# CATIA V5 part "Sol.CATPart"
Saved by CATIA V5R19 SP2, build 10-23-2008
Part number: Sol
Bounding box of the stored display mesh (mm): x 0 to 6000, y -177 to 177, z -68.836 to 0
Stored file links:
  E:\Mes documents\03_Ressources pédagogiques\01_Catia\Buggy Dassault\SchemaCinematiqueFinal\Sol.CATPart
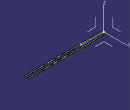
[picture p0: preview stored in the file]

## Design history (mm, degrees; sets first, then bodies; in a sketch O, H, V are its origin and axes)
AxisSystem1: origin (0, 0, 0), X (1, 0, 0), Y (0, 1, 0), Z (0, 0, 1)
Body1 (main body)
  Plane1: type Offset, RefPlane ZX plane of AxisSystem1, Offset 147
  Plane2: type Offset, RefPlane ZX plane of AxisSystem1, Offset 147, reversed
  Sketch1 on Plane1, origin (0, 147, 0), H (-1, 0, 0), V (0, 0, 1)
    spline S1 through (-2519.6694, 0) (-2595.23, 0) (-2761.0478, -2.7637) (-2976.8854, 36.2754) (-3314.4824, -16.625) (-3730.1819, 30.4209) (-3964.2934, -13.9903) (-4260.9327, 31.8924) (-4715.3639, -16.6283) (-4982.808, 0)
    line L1 (-2519.6694, 0) -> (0, 0)
    point P1 (-2519.6694, 0)
    point P2 (0, 0)
    line L2 (-4982.808, 0) -> (-6000, 0)
    point P3 (-4982.808, 0)
    point P4 (-6000, 0)
    reference projected point E1 (0, 0) from edge [YZ plane of AxisSystem1 | XY plane of AxisSystem1]
    construction line L3 through (-1352.9842, 40) direction (1, 0)
    construction line L4 through (-1749.0463, -20) direction (1, 0)
    point P9 (-2595.23, 0)
    point P10 (-2519.6694, 0)
    point P11 (-4982.808, 0)
    distance O P4 = 6000
    distance L1 L3 = 40
    distance L1 L4 = 20
    length L1 = 2519.6694
    coincidence: P9 H, P10 P1, L1 H, P11 P3, H L2, P2 E1
    horizontal: L1 H, L2 H, L3 H, L4 H
  Sketch2 on Plane2, origin (0, -147, 0), H (-1, 0, 0), V (0, 0, 1)
    projected line E1 (-6000, 0) -> (-4982.808, 0) from Sketch1.L2
    point P2 (-4982.808, 0)
    projected line E2 (-2519.6694, 0) -> (0, 0) from Sketch1.L1
    point P3 (-2519.6694, 0)
    spline S1 through (-2519.6694, 0) (-2884.6105, -14.8995) (-3189.8696, 31.2275) (-3484.5396, -2.4378) (-3790.7881, 29.3661) (-4235.8425, -14.7004) (-4607.1231, 28.934) (-4982.808, 0)
    construction line L1 through (-4288.3258, 40) direction (1, 0)
    construction line L2 through (-4014.2523, -20) direction (1, 0)
    point P9 (-2519.6694, 0)
    point P10 (-4982.808, 0)
    distance E1 L1 = 40
    distance E1 L2 = 20
    coincidence: P9 P3, P10 P2
    horizontal: L1 H, L2 H
  Extrude1: Element1 Sketch1, Lim1 60, Lim2 30, Direction Plane1
  Extrude2: Element1 Sketch2, Lim1 60, Lim2 30, Direction Plane2
  Offset1: Offset Extrude1, Length 50
  Offset2: Offset Extrude2, Length 50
